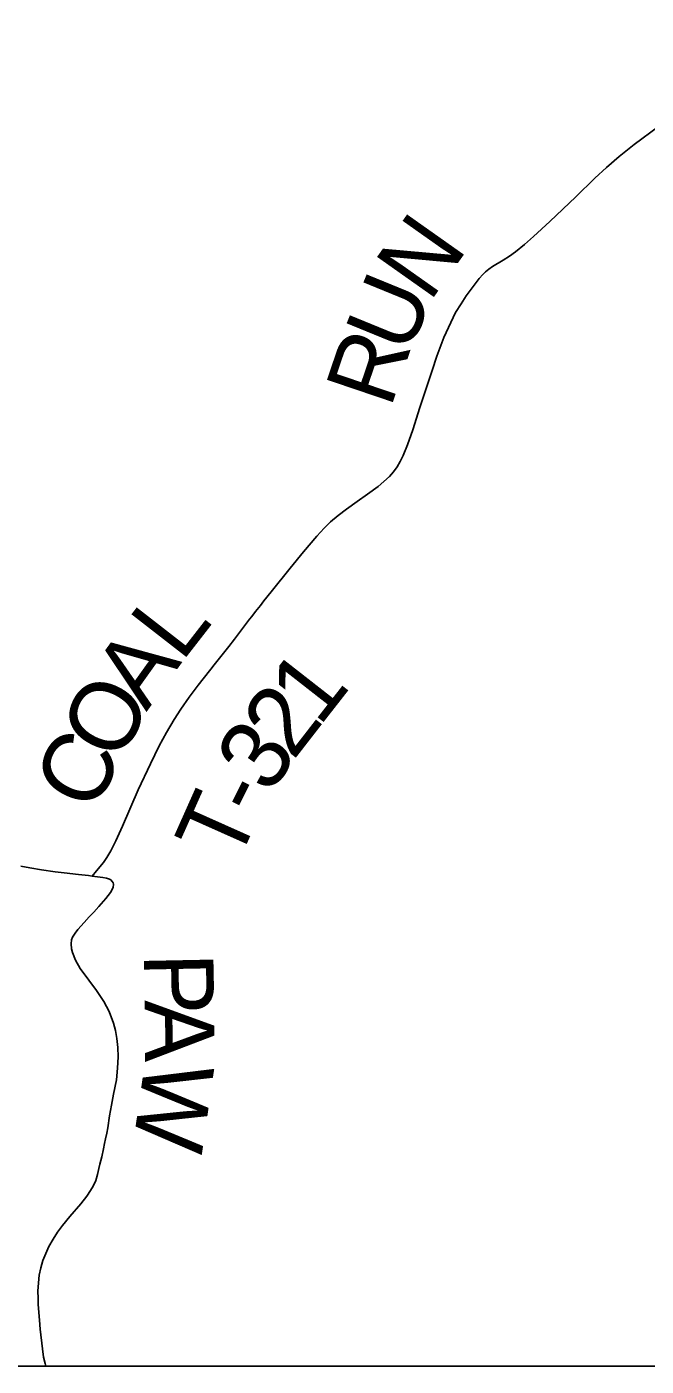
# Model space of a CAD drawing. Extents: x -10.5 to 40.6, y -3.2 to 22.
# Drawn here: x -7.773 to -7.268, y 14.1 to 15.194 of the extents above; entities that cross this region are included whole.
import ezdxf

# ---------------------------------------------------------------- set-up
doc = ezdxf.new("R2010")
doc.units = 0
for name, color, linetype in [('GM_X_Township_Road', 7, 'Continuous'), ('GM_X_Township_Road_Text', 7, 'Continuous'), ('SH_Text', 7, 'Continuous')]:
    doc.layers.add(name, color=color, linetype=linetype)

msp = doc.modelspace()

# ---------------------------------------------------------------- linework, layer by layer
at = {"layer": 'GM_X_Township_Road'}
for points in [[(-7.7197, 14.5001), (-7.7161, 14.5045), (-7.7106, 14.5112), (-7.7078, 14.5153), (-7.7046, 14.5207), (-7.7004, 14.529), (-7.695, 14.5409), (-7.6821, 14.5705), (-7.6722, 14.5919), (-7.6651, 14.6064), (-7.6591, 14.6173), (-7.6528, 14.628), (-7.6475, 14.6364), (-7.6407, 14.6461), (-7.6332, 14.656), (-7.624, 14.6677), (-7.6228, 14.6691), (-7.6201, 14.6725), (-7.6082, 14.6877), (-7.6037, 14.6936), (-7.5912, 14.7098), (-7.5893, 14.7122), (-7.5863, 14.7162), (-7.5824, 14.721), (-7.5795, 14.7249), (-7.5736, 14.7321), (-7.5581, 14.7514), (-7.5472, 14.765), (-7.5363, 14.7777), (-7.5304, 14.7841), (-7.5251, 14.7893), (-7.519, 14.7945), (-7.5121, 14.7998), (-7.5035, 14.806), (-7.4949, 14.812), (-7.4863, 14.8183), (-7.4816, 14.8223), (-7.4771, 14.8265), (-7.4738, 14.8303), (-7.4708, 14.8343), (-7.4683, 14.8385), (-7.4659, 14.8436), (-7.4624, 14.8522), (-7.458, 14.8645), (-7.4522, 14.8827), (-7.4422, 14.9129), (-7.4385, 14.9245), (-7.4327, 14.9399), (-7.4271, 14.952), (-7.4231, 14.9603), (-7.4186, 14.9674), (-7.4144, 14.9738), (-7.4088, 14.9815), (-7.4039, 14.9879), (-7.401, 14.9912), (-7.3988, 14.9934), (-7.396, 14.9957), (-7.3929, 14.9978), (-7.3843, 15.0029), (-7.3791, 15.0063), (-7.3742, 15.0099), (-7.3669, 15.0157), (-7.3594, 15.0222), (-7.3461, 15.0345), (-7.325, 15.0546), (-7.3095, 15.0699), (-7.2999, 15.0787), (-7.2895, 15.0876), (-7.2774, 15.0973), (-7.2575, 15.1122)], [(-7.7197, 14.5001), (-7.7228, 14.5005), (-7.7308, 14.5015), (-7.7425, 14.5029), (-7.7499, 14.5037), (-7.761, 14.5052), (-7.7707, 14.5069), (-7.7781, 14.5083)], [(-7.7575, 14.1), (-7.7582, 14.1021), (-7.7594, 14.1075), (-7.7604, 14.1143), (-7.7621, 14.1303), (-7.7628, 14.1377), (-7.7636, 14.147), (-7.7638, 14.1507), (-7.7639, 14.1556), (-7.764, 14.1612), (-7.7636, 14.168), (-7.7629, 14.1742), (-7.7616, 14.1803), (-7.7599, 14.1862), (-7.7577, 14.1921), (-7.755, 14.1977), (-7.7517, 14.2037), (-7.7481, 14.2094), (-7.744, 14.2149), (-7.738, 14.2221), (-7.7291, 14.2325), (-7.7241, 14.2388), (-7.721, 14.2434), (-7.7189, 14.247), (-7.7168, 14.2517), (-7.7153, 14.2564), (-7.7142, 14.2613), (-7.7134, 14.2649), (-7.7119, 14.2709), (-7.7105, 14.2776), (-7.7096, 14.2818), (-7.7088, 14.2855), (-7.7078, 14.2903), (-7.707, 14.2946), (-7.7055, 14.3043), (-7.704, 14.3131), (-7.7022, 14.322), (-7.7, 14.3338), (-7.699, 14.3432), (-7.6986, 14.3527), (-7.6989, 14.3602), (-7.6995, 14.3675), (-7.7006, 14.374), (-7.7022, 14.38), (-7.706, 14.3895), (-7.7102, 14.3977), (-7.7162, 14.4066), (-7.7226, 14.4153), (-7.7295, 14.4248), (-7.7333, 14.4315), (-7.7359, 14.4377), (-7.7366, 14.4408), (-7.7368, 14.4448), (-7.7365, 14.448), (-7.7357, 14.4504), (-7.7337, 14.4535), (-7.7315, 14.4564), (-7.7264, 14.4623), (-7.7222, 14.4668), (-7.7184, 14.4708), (-7.7144, 14.4752), (-7.7086, 14.4819), (-7.7049, 14.4868), (-7.7026, 14.4908), (-7.7023, 14.4935), (-7.7026, 14.4947), (-7.7033, 14.4957), (-7.7046, 14.497), (-7.7057, 14.4977), (-7.708, 14.4985), (-7.7111, 14.4989), (-7.7197, 14.5001)]]:
    msp.add_lwpolyline(points, dxfattribs=at)
at = {"layer": 'SH_Text'}
msp.add_lwpolyline([(-10.5445, 16.0741), (-10.5445, 14.1), (-6.2122, 14.1)], dxfattribs=at)

# ---------------------------------------------------------------- texts
at = {"layer": 'GM_X_Township_Road_Text'}
for s, rotation, p in [('N', 54.7528, (-7.4444, 14.9678)), ('U', 67.7366, (-7.4617, 14.9245)), ('R', 71.2861, (-7.4763, 14.8812)), ('L', 52.1307, (-7.6467, 14.6741)), ('A', 54.395, (-7.6755, 14.6339)), ('1', 51.9904, (-7.5344, 14.6214)), ('O', 62.0501, (-7.6978, 14.5915)), ('2', 52.1798, (-7.5558, 14.5938)), ('3', 55.4569, (-7.5751, 14.5657)), ('C', 62.6774, (-7.7192, 14.5502)), ('-', 63.3616, (-7.5845, 14.5466)), ('T', 65.9426, (-7.6016, 14.5084)), ('P', 271.131, (-7.6777, 14.4371)), ('A', 270.5756, (-7.677, 14.3989)), ('W', 261.7854, (-7.6763, 14.3512))]:
    msp.add_text(s, height=0.0568, rotation=rotation, dxfattribs=at).set_placement(p)

doc.saveas('drawing.dxf')
